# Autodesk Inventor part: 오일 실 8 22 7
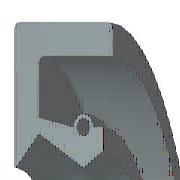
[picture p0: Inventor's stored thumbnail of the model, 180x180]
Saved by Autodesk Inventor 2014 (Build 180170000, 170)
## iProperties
IsCustomPart: 1
Created: 2012-02
Part Number: 오일 실 8 22 7
Material: 고무
Description: 오일-실
Document SubType Name: Modeling
Standard: KS B 2804
Designer: mduedu
Standards Organization: KS
Language: ko-KR
Size Designation: D - 8 22 7
Categories: <MemberInstance><Categories><Category DisplayName="샤프트 부품" InternalName="7f7aeb1f-a693-4053-b835-cee3144e0d98" Mnemonic="SHFT"><Category DisplayName="실링" Intern
Density: 0.93 g/cm^3
Appearance: 고무 - 검은색 - 버전 1.1
Mass: 1.28441 g
Surface Area: 18.2787 cm^2
Volume: 1.38108 cm^3
Author: mduedu
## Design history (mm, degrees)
revolve "본체" stored, may be unused: angle "d17" = 90 deg
revolve "스프링1" stored, may be unused: angle "d18" = 90 deg
body "Solid1"
sketch "스케치1"
  geometry: L1 (0, 11)-(7, 11); L2 (7, 9.25)-(1.75, 9.25); L3 (1.75, 5.75)-(4.9, 4); L4 (4.9, 4)-(0, 4); L5 (0, 0)-(9.586, 0) reference; L6 (4.9, 4)-(6.3, 4.875); L7 (0, 18)-(0, -3) reference; L8 (-1.941, 0)-(11.507, 0) reference; L9 (4.2, 6.1)-(1.75, 6.59); L10 (1.75, 6.59)-(1.75, 9.25); L11 (0, 11)-(0, 4.088); L12 (4.9, 4)-(0, 4); L13 (1.75, 5.75)-(0.152, 4.028); L14 (7, 11)-(7, 9.25); L15 (5.6, 6.1)-(6.3, 6.1); L16 (6.3, 6.1)-(6.3, 4.875); C1 r 0.455 at (4.9, 6.1); A1 r 0.7 centre (4.9, 6.1) between (5.6, 6.1) and (4.2, 6.1); A2 r 0.088 centre (0.088, 4.088) between (0, 4.088) and (0.152, 4.028); 1 further point
  constraints: 28 end point, 5 horizontal alignment, 5 point on line, 4 point on circle, 4 vertical alignment, 3 centre point, 3 tangent, 2 collinear, 2 horizontal, 2 perpendicular, 1 coincident, 1 parallel
  dimensions: "d0" = 22 diameter of L1 L5 (= SD2); "d1" = 1.75 distance of L1.end L2.start (= SD); "d2" = 0.91 diameter of C1 (= SPDI); "d3" = 1.4 diameter of A1 (= SPDA); "d4" = 8 diameter of L3.end L5 (= NND); "d5" = 11.5 diameter of L3.start L5 (= TKDM); "d7" = 13.18 diameter of L9.end L5 (= TKDM + 0.24 x SWDT); "d8" = 1.75 distance between parallel lines of L11 L10 (= SD); "d9" = 4.9 distance from line of L11 C1.centre (= SPDST); "d10" = 12.2 diameter of C1.centre L5 (= HLDM); "d11" = 0.0875 radius of A2 (= 0.25 x LAB); "d12" = 6.3 distance between parallel lines of L11 L16 (= SDI); "d13" = 9.75 diameter of L6.end L5 (= ABDM); "d14" = 7 distance from line of L11 L1.end (= SWDT)
fillet "모깎기1" dims "d6" = 0.3 (= RR)
other parameters: "SD2" = 22 [user parameter; used in 1 equation term], "SWDT" = 7 [user parameter; used in 2 equation terms], "RR" = 0.3 [user parameter; used in 1 equation term], "SD" = 1.75 [user parameter; used in 2 equation terms], "NND" = 8 [user parameter; used in 1 equation term], "SPDA" = 1.4 [user parameter; used in 1 equation term], "SPDI" = 0.91 [user parameter; used in 1 equation term], "TKDM" = 11.5 [user parameter; used in 2 equation terms], "HLDM" = 12.2 [user parameter; used in 1 equation term], "ABDM" = 9.75 [user parameter; used in 1 equation term], "SDI" = 6.3 [user parameter; used in 1 equation term], "SPDST" = 4.9 [user parameter; used in 1 equation term], "LAB" = 0.35 [user parameter; used in 1 equation term], "d15" = 0, "d16" = 0, "d19" = 0
